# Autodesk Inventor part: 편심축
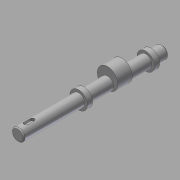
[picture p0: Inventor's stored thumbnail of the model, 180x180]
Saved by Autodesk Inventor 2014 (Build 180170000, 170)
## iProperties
Created: 2016-02
Part Number: 편심축
Material: 강철, 연강
Document SubType Name: Modeling
Designer: mduedu
Density: 1 g/cm^3
Appearance: Steel
Author: mduedu
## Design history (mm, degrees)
sketch "스케치1"
  geometry: C1 r 6 at (0, 0); 1 further point
  constraints: 1 centre point, 1 coincident
  dimensions: "d0" = 12 diameter of C1
extrude "돌출1" new body sketch "스케치1" distance "d1" = 140; taper "d2" = 0 deg
chamfer "모따기1" distance "d3" = 1; stored, may be unused: second distance "d4" = 2, angle "d5" = 45 deg
node "작업 평면1"
sketch "스케치2"
  geometry: C1 r 10 at (0, 4); C2 r 6 at (0, 0) reference; 1 further point
  constraints: 1 centre point, 1 tangent, 1 vertical alignment
  dimensions: "d7" = 20 diameter of C1
extrude "돌출2" join sketch "스케치2" stored distance "d8" = 14; taper "d9" = 0 deg
node "작업 평면2"
sketch "스케치3"
  geometry: C1 r 8.5 at (0, 0); 1 further point
  constraints: 1 centre point, 1 coincident
  dimensions: "d12" = 17 diameter of C1
extrude "돌출3" join sketch "스케치3" distance "d13" = 5; taper "d14" = 0 deg
node "작업 평면3"
sketch "스케치4"
  geometry: L1 (-5, 140)-(5, 140) reference; L2 (0, 140)-(0, 0); L3 (-2, 132)-(-2, 126); L4 (2, 126)-(2, 132); A1 r 2 centre (0, 132) between (2, 132) and (-2, 132); A2 r 2 centre (0, 126) between (-2, 126) and (2, 126)
  constraints: 6 end point, 4 point on circle, 4 tangent, 2 centre point, 2 point on line, 1 midpoint, 1 parallel, 1 perpendicular
  dimensions: "d15" = 4 distance between parallel lines of L3 L4; "d17" = 6 distance edge to line of A1 L1; "d18" = 10 dimension on A2 A1
extrude "돌출4" cut sketch "스케치4" distance "d19" = 2.5; taper "d20" = 0 deg
sketch "스케치5"
  geometry: L1 (6, 53)-(6, 139) reference; L2 (-6, 53)-(-6, 139) reference; L3 (6, 115)-(-6, 115); L4 (-5, 140)-(5, 140) reference; L5 (6, 116.5)-(4.5, 115); L6 (6, 116.5)-(6, 115); L7 (4.5, 115)-(6, 115); 1 further point
  constraints: 8 end point, 4 point on line, 2 collinear, 1 perpendicular
  dimensions: "d21" = 25 distance between parallel lines of L3 L4; "d22" = 3 diameter of L5.start L3; "d24" = 45 deg angle of L3 L5
revolve "회전1" sketch "스케치5" stored, may be unused: angle "d25" = 90 deg
sketch "스케치6"
  geometry: L1 (6, 116.5)-(4.5, 115) reference; L2 (6, 113.5)-(4.5, 115) reference; 2 further points
  constraints: 1 coincident
node "작업 평면4"
sketch "스케치7"
  geometry: C1 r 8.5 at (0, -4); 1 further point
  constraints: 1 centre point, 1 coincident
  dimensions: "d27" = 17 diameter of C1
extrude "돌출5" join sketch "스케치7" distance "d29" = 5; taper "d30" = 0 deg
node "솔리드1"
other parameters: "d6" = -46, "d11" = -11, "d26" = 28
